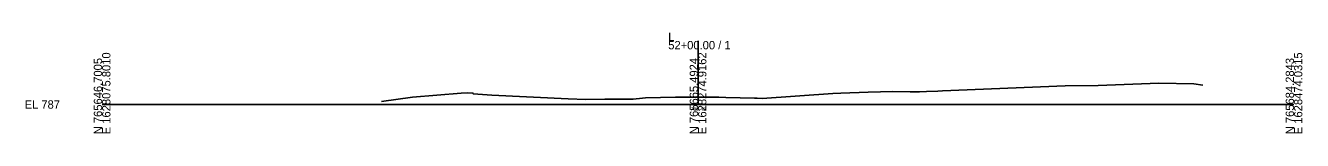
# Model space of a CAD drawing. Extents: x -26 to 4403, y -510 to 9556.
# Drawn here: x 3974.3 to 4402.8, y 1990.3 to 2024.1 of the extents above; entities that cross this region are included whole.
import ezdxf

# ---------------------------------------------------------------- set-up
doc = ezdxf.new("R2010")
doc.units = 0
for name, color, linetype in [('Default', 7, 'Continuous'), ('Exist Cross Section Cell', 7, 'Continuous'), ('Exist XS Center Line Elevation Label', 7, 'Continuous'), ('Exist XS Ground Line', 7, 'Continuous')]:
    doc.layers.add(name, color=color, linetype=linetype)

msp = doc.modelspace()

# ---------------------------------------------------------------- linework, layer by layer
at = {"layer": 'Exist Cross Section Cell'}
for p, q in [((4200, 2000), (4200, 2021.31)), ((4000, 2000), (4200, 2000)), ((4200, 2000), (4400, 2000))]:
    msp.add_line(p, q, dxfattribs=at)
at = {"layer": 'Exist XS Ground Line'}
msp.add_lwpolyline([(4093.77, 2001.02), (4104.15, 2002.47), (4120.54, 2003.77), (4122.69, 2003.89), (4124.45, 2003.82), (4124.54, 2003.62), (4130.76, 2003.17), (4156.44, 2001.88), (4162.32, 2001.66), (4168.76, 2001.83), (4178.25, 2001.83), (4181.34, 2002.14), (4182.35, 2002.23), (4192.44, 2002.42), (4194.85, 2002.47), (4197.19, 2002.47), (4200, 2002.46), (4206.96, 2002.45), (4209.37, 2002.39), (4218.99, 2002.16), (4219.87, 2002.12), (4221.56, 2002.04), (4245.18, 2003.67), (4247.91, 2003.83), (4257.09, 2004.14), (4265.39, 2004.33), (4271.18, 2004.25), (4274.31, 2004.27), (4276.65, 2004.34), (4280.48, 2004.44), (4282.04, 2004.59), (4323.26, 2006.26), (4334.23, 2006.33), (4354.67, 2007.1), (4366.37, 2006.92), (4369.4, 2006.5)], dxfattribs=at)

# ---------------------------------------------------------------- texts
at = {"layer": 'Default'}
msp.add_text('-', height=0.0001, dxfattribs=at).set_placement((4000, 2000))
at = {"layer": 'Exist Cross Section Cell'}
for s, p in [('L', (4190, 2021.31)), ('52+00.00 / 1', (4190, 2018.51)), ('EL 787', (3974, 1998.6))]:
    msp.add_text(s, height=2.8, dxfattribs=at).set_placement(p)
for s, p in [('N 765646.7005', (4000, 1990)), ('E 1628075.8010', (4002.8, 1990)), ('N 765665.4924', (4200, 1990)), ('E 1628274.9162', (4202.8, 1990)), ('N 765684.2843', (4400, 1990)), ('E 1628474.0315', (4402.8, 1990))]:
    msp.add_text(s, height=2.8, rotation=90, dxfattribs=at).set_placement(p)
at = {"layer": 'Exist XS Center Line Elevation Label'}
msp.add_text('789.46', height=1.2, dxfattribs=at).set_placement((4197.52, 1997.86))

doc.saveas('drawing.dxf')
